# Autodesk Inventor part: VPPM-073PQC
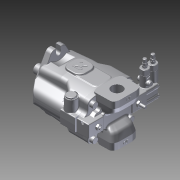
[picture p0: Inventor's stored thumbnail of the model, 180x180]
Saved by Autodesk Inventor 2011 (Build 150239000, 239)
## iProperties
Created: 2013-02
Part Number: VPPM-073PQC
Document SubType Name: Modeling
Designer: khramov
Density: 1 g/cm^3
Стандарт преобразования: STEP AP214IS
Имя файла: C:\Documents and Settings\sgaravagli\Desktop\06865605_asm_stp_Shrinkwrap_8.stp
Препроцессор: Autodesk Inventor 2013
Постпроцессор: Build: 239, Release: 2011 RTM - Date: Wed 02/17/2010
Отправленные единицы: миллиметр
Неопределенность: 0.01
Author: khramov
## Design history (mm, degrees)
feature "БазТело1"
sketch "Эскиз1"
  geometry: L1 (327.47, 38.511)-(327.47, 6.511) reference; L2 (327.47, 22.511)-(-88.73, 22.511); L3 (268.2, -6.489)-(268.2, -41.336) reference; C1 r 15 at (33.2, 22.511); 1 further point
  constraints: 2 end point, 1 centre point, 1 midpoint, 1 perpendicular, 1 point on line
  dimensions: "d0" = 235 distance from line of C1.centre L3; "d1" = 30 diameter of C1
extrude "Выдавливание1" cut sketch "Эскиз1" distance "d2" = 30; taper "d3" = 0 deg
sketch "Эскиз2"
  geometry: L1 (-335.47, 13.011)-(-335.47, 45.011) reference; L2 (-335.47, 29.011)-(73.416, 29.011); L3 (-41, 41.006)-(-41, 17.016) reference; C1 r 20 at (-41, 29.011); 1 further point
  constraints: 2 end point, 2 midpoint, 1 centre point, 1 perpendicular
  dimensions: "d4" = 40 diameter of C1
extrude "Выдавливание2" cut sketch "Эскиз2" distance "d5" = 30; taper "d6" = 0 deg
sketch "Эскиз3"
  geometry: A1 r 17.339 centre (17.339, 10.491) between (4.231, 21.841) and (0, 10.491) reference; 2 further points
  constraints: 1 coincident
hole "Отверстие1" sketch "Эскиз3" at (17.339, 10.491) diameter "d7" = 18.631; stored, may be unused: countersink angle "d11" = 90 deg, drill point angle "d13" = 118 deg; dims "d8" = 6, "d9" = 4, "d10" = 2, "d12" = 40
node "Solido1"
